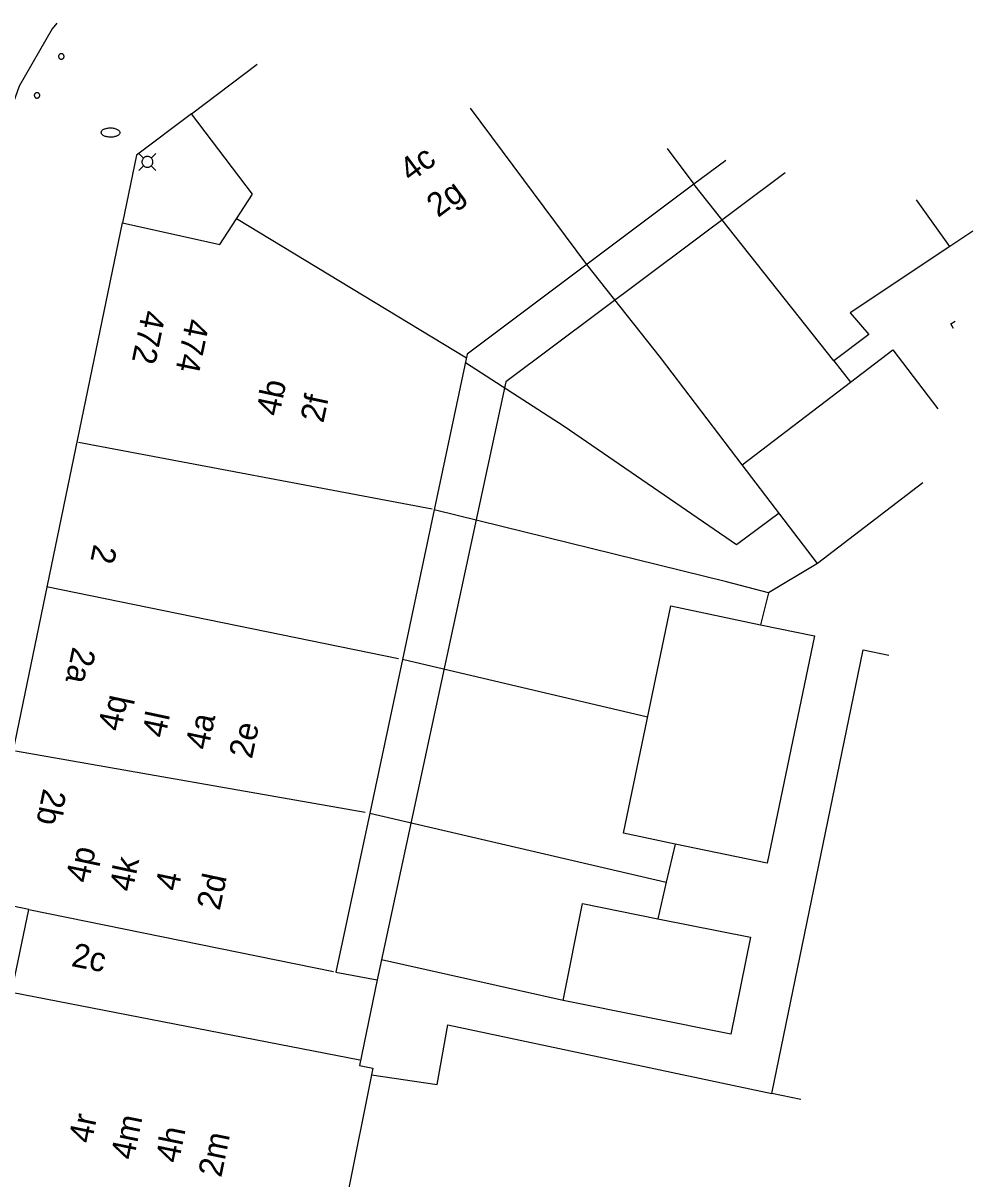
# Model space of a CAD drawing. Extents: x 81065 to 81486, y 452384 to 452681.
# Drawn here: x 81293.34 to 81325.27, y 452580.7 to 452619.54 of the extents above; entities that cross this region are included whole.
import ezdxf

# ---------------------------------------------------------------- set-up
doc = ezdxf.new("R2010")
doc.units = 0
for name, color, linetype in [('B-BH-AL-TOPOGRAFIE_HUISNUMMER-T25', 7, 'Continuous'), ('B-BH-IE-MEUBILAIR_WEGMEUBILAIR_PAAL-S', 7, 'Continuous'), ('B-BH-KL-WATER_BRANDLEIDING_PUT-S', 7, 'Continuous'), ('B-BH-OG-TERREIN_ERF-GV', 7, 'Continuous'), ('B-BH-OG-TOPOGRAFIE_BEBOUWING-GV', 7, 'Continuous'), ('B-BH-OG-TOPOGRAFIE_BEBOUWING_PANDSCHEIDING-GV', 7, 'Continuous'), ('B-BH-VH-KANTOPSLUITING-GV', 7, 'Continuous')]:
    doc.layers.add(name, color=color, linetype=linetype)

msp = doc.modelspace()

# ---------------------------------------------------------------- linework, layer by layer
at = {"layer": 'B-BH-IE-MEUBILAIR_WEGMEUBILAIR_PAAL-S'}
for points in [[(81294.532, 452618.422), (81294.533, 452618.412), (81294.534, 452618.403), (81294.537, 452618.393), (81294.54, 452618.384), (81294.544, 452618.376), (81294.55, 452618.368), (81294.556, 452618.36), (81294.562, 452618.354), (81294.57, 452618.348), (81294.578, 452618.342), (81294.587, 452618.338), (81294.595, 452618.335), (81294.605, 452618.332), (81294.614, 452618.331), (81294.624, 452618.33), (81294.633, 452618.331), (81294.643, 452618.332), (81294.652, 452618.335), (81294.661, 452618.338), (81294.67, 452618.342), (81294.678, 452618.348), (81294.685, 452618.354), (81294.692, 452618.36), (81294.698, 452618.368), (81294.703, 452618.376), (81294.707, 452618.384), (81294.711, 452618.393), (81294.713, 452618.403), (81294.715, 452618.412), (81294.715, 452618.422), (81294.715, 452618.431), (81294.713, 452618.441), (81294.711, 452618.45), (81294.707, 452618.459), (81294.703, 452618.467), (81294.698, 452618.475), (81294.692, 452618.483), (81294.685, 452618.49), (81294.678, 452618.496), (81294.67, 452618.501), (81294.661, 452618.505), (81294.652, 452618.509), (81294.643, 452618.511), (81294.633, 452618.513), (81294.624, 452618.513), (81294.614, 452618.513), (81294.605, 452618.511), (81294.595, 452618.509), (81294.587, 452618.505), (81294.578, 452618.501), (81294.57, 452618.496), (81294.562, 452618.49), (81294.556, 452618.483), (81294.55, 452618.475), (81294.544, 452618.467), (81294.54, 452618.459), (81294.537, 452618.45), (81294.534, 452618.441), (81294.533, 452618.431), (81294.532, 452618.422)], [(81293.715, 452617.113), (81293.716, 452617.103), (81293.717, 452617.094), (81293.72, 452617.084), (81293.723, 452617.075), (81293.727, 452617.067), (81293.733, 452617.059), (81293.739, 452617.051), (81293.745, 452617.045), (81293.753, 452617.039), (81293.761, 452617.033), (81293.77, 452617.029), (81293.778, 452617.026), (81293.788, 452617.023), (81293.797, 452617.022), (81293.807, 452617.021), (81293.816, 452617.022), (81293.826, 452617.023), (81293.835, 452617.026), (81293.844, 452617.029), (81293.853, 452617.033), (81293.861, 452617.039), (81293.868, 452617.045), (81293.875, 452617.051), (81293.881, 452617.059), (81293.886, 452617.067), (81293.89, 452617.075), (81293.894, 452617.084), (81293.896, 452617.094), (81293.898, 452617.103), (81293.898, 452617.113), (81293.898, 452617.122), (81293.896, 452617.132), (81293.894, 452617.141), (81293.89, 452617.15), (81293.886, 452617.158), (81293.881, 452617.166), (81293.875, 452617.174), (81293.868, 452617.181), (81293.861, 452617.187), (81293.853, 452617.192), (81293.844, 452617.196), (81293.835, 452617.2), (81293.826, 452617.202), (81293.816, 452617.204), (81293.807, 452617.204), (81293.797, 452617.204), (81293.788, 452617.202), (81293.778, 452617.2), (81293.77, 452617.196), (81293.761, 452617.192), (81293.753, 452617.187), (81293.745, 452617.181), (81293.739, 452617.174), (81293.733, 452617.166), (81293.727, 452617.158), (81293.723, 452617.15), (81293.72, 452617.141), (81293.717, 452617.132), (81293.716, 452617.122), (81293.715, 452617.113)]]:
    msp.add_lwpolyline(points, dxfattribs=at)
at = {"layer": 'B-BH-KL-WATER_BRANDLEIDING_PUT-S'}
msp.add_lwpolyline([(81296.279, 452616.01), (81296.245, 452616.009), (81296.212, 452616.007), (81296.18, 452616.003), (81296.148, 452615.998), (81296.118, 452615.991), (81296.09, 452615.983), (81296.064, 452615.974), (81296.04, 452615.963), (81296.019, 452615.951), (81296, 452615.939), (81295.985, 452615.925), (81295.973, 452615.911), (81295.964, 452615.897), (81295.959, 452615.882), (81295.957, 452615.866), (81295.959, 452615.851), (81295.964, 452615.836), (81295.972, 452615.821), (81295.984, 452615.807), (81295.999, 452615.793), (81296.018, 452615.78), (81296.039, 452615.768), (81296.062, 452615.757), (81296.088, 452615.748), (81296.117, 452615.739), (81296.146, 452615.732), (81296.178, 452615.726), (81296.21, 452615.722), (81296.243, 452615.719), (81296.277, 452615.718), (81296.31, 452615.719), (81296.344, 452615.721), (81296.376, 452615.725), (81296.408, 452615.73), (81296.438, 452615.737), (81296.466, 452615.745), (81296.492, 452615.754), (81296.516, 452615.765), (81296.537, 452615.776), (81296.555, 452615.789), (81296.571, 452615.802), (81296.583, 452615.817), (81296.592, 452615.831), (81296.597, 452615.846), (81296.599, 452615.861), (81296.597, 452615.877), (81296.592, 452615.892), (81296.584, 452615.907), (81296.572, 452615.921), (81296.557, 452615.935), (81296.538, 452615.947), (81296.517, 452615.96), (81296.494, 452615.971), (81296.468, 452615.98), (81296.439, 452615.989), (81296.409, 452615.996), (81296.378, 452616.002), (81296.346, 452616.006), (81296.313, 452616.009), (81296.279, 452616.01)], dxfattribs=at)
at = {"layer": 'B-BH-OG-TERREIN_ERF-GV'}
for p, q in [((81320.586, 452608.191), (81315.89, 452614.124)), ((81324.494, 452612.035), (81323.369, 452613.606)), ((81317.319, 452602.023), (81318.749, 452603.078)), ((81314.33, 452596.214), (81306.09, 452598.158)), ((81304.99, 452592.989), (81314.96, 452590.665))]:
    msp.add_line(p, q, dxfattribs=at)
for points in [[(81317.514, 452604.694), (81314.766, 452608.3), (81312.291, 452611.426)], [(81308.211, 452608.131), (81311.532, 452605.995), (81317.319, 452602.023)], [(81318.398, 452600.396), (81316.984, 452600.766), (81307.159, 452603.189)]]:
    msp.add_lwpolyline(points, dxfattribs=at)
at = {"layer": 'B-BH-OG-TOPOGRAFIE_BEBOUWING-GV'}
for p, q in [((81298.997, 452616.496), (81297.148, 452615.107)), ((81297.148, 452615.107), (81296.676, 452612.828)), ((81297.231, 452615.164), (81297.387, 452615.007)), ((81297.646, 452615.007), (81297.803, 452615.164)), ((81297.387, 452614.748), (81297.231, 452614.592)), ((81297.646, 452614.748), (81297.803, 452614.592)), ((81319.481, 452583.363), (81318.511, 452583.562))]:
    msp.add_line(p, q, dxfattribs=at)
for points in [[(81286.276, 452538.555), (81285.609, 452539.778), (81285.995, 452539.989), (81283.022, 452545.459), (81287.25, 452565.297), (81286.821, 452565.397), (81288.147, 452571.707), (81289.4, 452571.444), (81292.656, 452587.012), (81292.95, 452586.951), (81293.53, 452589.752), (81291.963, 452590.077), (81296.676, 452612.828), (81299.951, 452612.1), (81301.047, 452613.797), (81298.997, 452616.496), (81301.21, 452618.158)], [(81297.334, 452614.878), (81297.335, 452614.859), (81297.338, 452614.84), (81297.343, 452614.821), (81297.35, 452614.803), (81297.358, 452614.786), (81297.369, 452614.77), (81297.381, 452614.755), (81297.394, 452614.742), (81297.409, 452614.73), (81297.425, 452614.719), (81297.442, 452614.711), (81297.46, 452614.704), (81297.479, 452614.699), (81297.498, 452614.696), (81297.517, 452614.695), (81297.536, 452614.696), (81297.555, 452614.699), (81297.574, 452614.704), (81297.591, 452614.711), (81297.608, 452614.719), (81297.625, 452614.73), (81297.639, 452614.742), (81297.653, 452614.755), (81297.665, 452614.77), (81297.675, 452614.786), (81297.684, 452614.803), (81297.691, 452614.821), (81297.696, 452614.84), (81297.699, 452614.859), (81297.7, 452614.878), (81297.699, 452614.897), (81297.696, 452614.916), (81297.691, 452614.935), (81297.684, 452614.952), (81297.675, 452614.969), (81297.665, 452614.986), (81297.653, 452615), (81297.639, 452615.014), (81297.625, 452615.026), (81297.608, 452615.036), (81297.591, 452615.045), (81297.574, 452615.052), (81297.555, 452615.057), (81297.536, 452615.06), (81297.517, 452615.061), (81297.498, 452615.06), (81297.479, 452615.057), (81297.46, 452615.052), (81297.442, 452615.045), (81297.425, 452615.036), (81297.409, 452615.026), (81297.394, 452615.014), (81297.381, 452615), (81297.369, 452614.986), (81297.358, 452614.969), (81297.35, 452614.952), (81297.343, 452614.935), (81297.338, 452614.916), (81297.335, 452614.897), (81297.334, 452614.878)], [(81316.957, 452614.923), (81315.89, 452614.124), (81308.271, 452608.413), (81307.159, 452603.189), (81306.09, 452598.158), (81304.99, 452592.989), (81303.853, 452587.64), (81305.236, 452587.387)], [(81318.951, 452614.514), (81309.571, 452607.488), (81305.236, 452587.387)], [(81324.617, 452609.275), (81324.521, 452609.435), (81324.666, 452609.524)], [(81321.154, 452607.474), (81322.571, 452608.558), (81324.083, 452606.58)], [(81320.046, 452601.38), (81317.514, 452604.694), (81321.154, 452607.474)], [(81323.588, 452604.087), (81320.046, 452601.38)], [(81315.259, 452591.949), (81313.516, 452592.312), (81315.11, 452599.952), (81318.123, 452599.323)], [(81318.123, 452599.323), (81319.939, 452598.944), (81318.345, 452591.305), (81315.259, 452591.949)], [(81318.511, 452583.562), (81321.573, 452598.478), (81322.441, 452598.3)], [(81311.491, 452586.689), (81312.143, 452589.949), (81314.679, 452589.441)], [(81314.679, 452589.441), (81317.787, 452588.818), (81317.134, 452585.559), (81311.491, 452586.689)], [(81305.236, 452587.387), (81304.651, 452584.508), (81305.095, 452584.423), (81305.05, 452584.196)], [(81305.05, 452584.196), (81304.256, 452580.227), (81303.447, 452576.388)]]:
    msp.add_lwpolyline(points, dxfattribs=at)
at = {"layer": 'B-BH-OG-TOPOGRAFIE_BEBOUWING_PANDSCHEIDING-GV'}
for p, q in [((81312.291, 452611.426), (81308.379, 452616.685)), ((81314.985, 452615.328), (81315.89, 452614.124)), ((81308.243, 452608.283), (81300.512, 452612.968)), ((81307.084, 452603.203), (81295.206, 452605.442)), ((81294.129, 452600.602), (81305.954, 452598.186)), ((81304.838, 452593.016), (81293.085, 452595.076)), ((81293.529, 452589.752), (81303.776, 452587.666)), ((81304.658, 452584.683), (81292.953, 452586.963))]:
    msp.add_line(p, q, dxfattribs=at)
at = {"layer": 'B-BH-VH-KANTOPSLUITING-GV'}
for p, q in [((81325.266, 452612.549), (81324.494, 452612.035)), ((81320.586, 452608.191), (81321.154, 452607.474)), ((81320.046, 452601.38), (81318.398, 452600.396)), ((81318.398, 452600.396), (81318.123, 452599.323)), ((81315.259, 452591.949), (81314.96, 452590.665)), ((81314.96, 452590.665), (81314.679, 452589.441)), ((81305.381, 452588.058), (81305.236, 452587.387)), ((81311.491, 452586.689), (81305.381, 452588.058))]:
    msp.add_line(p, q, dxfattribs=at)
for points in [[(81294.472, 452619.542), (81294.312, 452619.352), (81293.208, 452617.422), (81292.493, 452615.43), (81291.34, 452609.906)], [(81324.494, 452612.035), (81321.144, 452609.805), (81321.772, 452609.075), (81320.586, 452608.191)], [(81305.05, 452584.196), (81307.258, 452583.865), (81307.615, 452585.876), (81318.511, 452583.562)]]:
    msp.add_lwpolyline(points, dxfattribs=at)

# ---------------------------------------------------------------- texts
at = {"layer": 'B-BH-AL-TOPOGRAFIE_HUISNUMMER-T25'}
for s, rotation, p in [('4c', 36.8514, (81306.369, 452614.173)), ('2g', 36.8514, (81307.286, 452612.986)), ('472', 258.2997, (81297.353, 452609.929)), ('474', 258.2997, (81298.826, 452609.645)), ('4b', 77.9933, (81301.944, 452606.3)), ('2f', 77.9933, (81303.43, 452606.078)), ('2', 258.2959, (81295.72, 452602.052)), ('2a', 258.2959, (81295.006, 452598.604)), ('4q', 77.9933, (81296.624, 452595.708)), ('4l', 77.9933, (81298.111, 452595.488)), ('4a', 77.9933, (81299.558, 452595.084)), ('2e', 77.9933, (81301.029, 452594.789)), ('2b', 258.2959, (81294.019, 452593.841)), ('4p', 77.9933, (81295.54, 452590.612)), ('4k', 77.9933, (81297.011, 452590.317)), ('4', 77.9933, (81298.549, 452590.339)), ('2d', 77.9933, (81299.945, 452589.693)), ('2c', 348.9756, (81294.93, 452587.853)), ('4r', 78.3983, (81295.639, 452581.861)), ('4m', 78.3983, (81297.056, 452581.306)), ('4h', 78.3983, (81298.566, 452581.2)), ('2m', 78.3983, (81299.998, 452580.72))]:
    msp.add_text(s, height=0.8, rotation=rotation, dxfattribs=at).set_placement(p)

doc.saveas('drawing.dxf')
